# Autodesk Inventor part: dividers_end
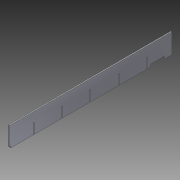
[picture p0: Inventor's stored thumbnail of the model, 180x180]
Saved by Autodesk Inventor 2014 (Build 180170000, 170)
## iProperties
Created: 2014-05
Part Number: dividers_end
Material: ABS Plastic
Document SubType Name: Modeling
Designer: t_emanb
Density: 1 g/cm^3
Appearance: Smooth - White
Author: t_emanb
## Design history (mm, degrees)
sketch "Sketch1"
  geometry: L1 (0, 0)-(72.39, 0); L2 (72.39, 0)-(72.39, -584.2); L3 (72.39, -584.2)-(0, -584.2); L4 (0, -584.2)-(0, 0); 1 further point
  constraints: 8 end point, 2 parallel, 1 coincident, 1 horizontal, 1 perpendicular
  dimensions: "d0" = 584.2 distance of L1.end L2.end; "d1" = 72.39 distance of L1.start L1.end
extrude "Extrusion1" new body sketch "Sketch1" distance "d2" = 3.048; taper "d3" = 0 deg
sketch "Sketch2" dims "d9" = 25.4, "d18" = 25.4
  geometry: L1 (0, 0)-(584.2, 0) reference; L2 (584.2, 72.39)-(0, 72.39) reference; L3 (88.9, 72.39)-(88.9, 0); L4 (190.5, 72.39)-(190.5, 0); L5 (292.1, 72.39)-(292.1, 0); L6 (393.7, 72.39)-(393.7, 0); L7 (495.3, 72.39)-(495.3, 0); L8 (87.376, 0)-(90.424, 0); L9 (90.424, 0)-(90.424, 38.1); L10 (90.424, 38.1)-(87.376, 38.1); L11 (87.376, 38.1)-(87.376, 0); L12 (188.976, 38.1)-(188.976, 0); L13 (192.024, 38.1)-(188.976, 38.1); L14 (192.024, 0)-(192.024, 38.1); L15 (188.976, 0)-(192.024, 0); L16 (290.576, 38.1)-(290.576, 0); L17 (293.624, 38.1)-(290.576, 38.1); L18 (293.624, 0)-(293.624, 38.1); L19 (290.576, 0)-(293.624, 0); L20 (392.176, 38.1)-(392.176, 0); L21 (395.224, 38.1)-(392.176, 38.1); L22 (395.224, 0)-(395.224, 38.1); L23 (392.176, 0)-(395.224, 0); L24 (493.776, 38.1)-(493.776, 0); L25 (496.824, 38.1)-(493.776, 38.1); L26 (496.824, 0)-(496.824, 38.1); L27 (493.776, 0)-(496.824, 0)
  constraints: 50 end point, 3 horizontal, 3 point on line, 2 parallel, 2 perpendicular, 1 midpoint, 45 other
  dimensions: "d6" = 101.6 distance of L3.start L4.start; "d11" = 3.048 distance of L9.end L10.end; "d12" = 38.1 distance of L10.end L8.start; "d15" = 101.6 distance of L10.end L12.start
extrude "Extrusion2" cut sketch "Sketch2" stored distance "d20" = 3.175; taper "d21" = 0 deg
sketch "Sketch3"
  geometry: L1 (496.824, 0)-(584.2, 0) reference; L2 (584.2, 0)-(584.2, 72.39) reference; L3 (0, 72.39)-(0, 0) reference; L4 (0, 0)-(87.376, 0) reference; L5 (392.176, 0)-(392.176, 38.1) reference; L6 (0, 6.35)-(6.35, 6.35); L7 (6.35, 6.35)-(6.35, 0)
  constraints: 4 end point, 2 perpendicular, 2 point on line
  dimensions: "d26" = 6.35 distance of L6.end L7.end; "d27" = 6.35 distance of L6.start L6.end
extrude "Extrusion3" cut sketch "Sketch3" stored distance "d24" = 25.4; taper "d25" = 0 deg
sketch "Sketch4"
  geometry: L1 (496.824, 0)-(584.2, 0) reference; L2 (584.2, 0)-(584.2, 72.39) reference; L3 (558.8, 9.525)-(508, 9.525); L4 (508, 9.525)-(508, 0); L5 (558.8, 9.525)-(558.8, 0); 1 further point
  constraints: 6 end point, 2 perpendicular, 2 point on line
  dimensions: "d28" = 50.8 distance of L3.start L3.end; "d29" = 9.525 distance between parallel lines of L1 L3; "d30" = 25.4 distance between parallel lines of L2 L5
extrude "Extrusion4" cut sketch "Sketch4" stored distance "d31" = 25.4; taper "d32" = 0 deg
body "Solid1"
